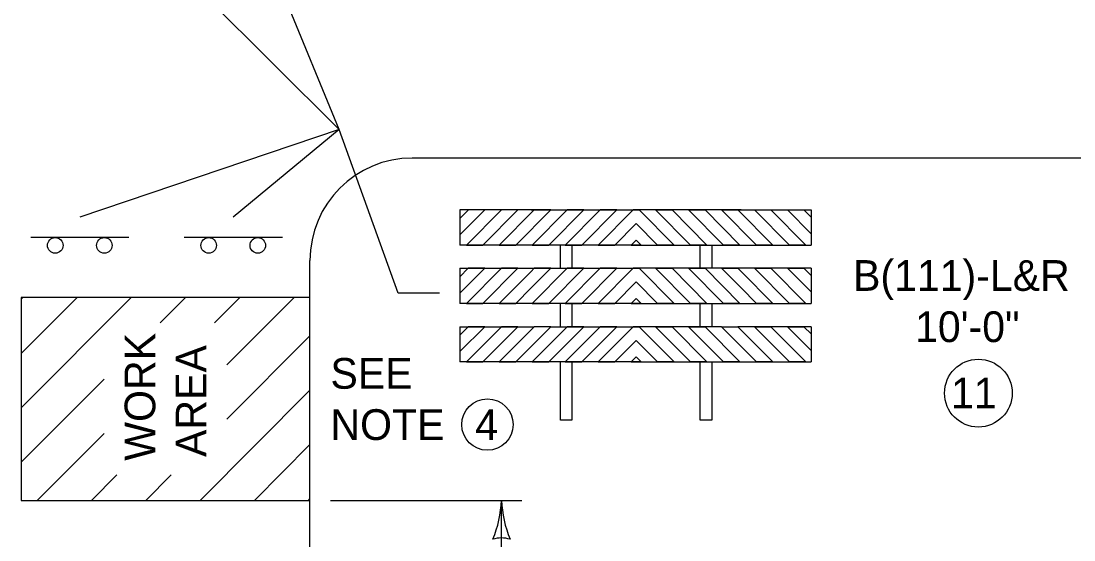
# Model space of a CAD drawing. Extents: x 49991.4 to 50021, y 49987.6 to 50011.4.
# Drawn here: x 50001.903 to 50003.961, y 49992.395 to 49993.408 of the extents above; entities that cross this region are included whole.
import ezdxf

# ---------------------------------------------------------------- set-up
doc = ezdxf.new("R2010")
doc.units = 0
for name, color, linetype in [('Level 1', 7, 'Continuous'), ('Level 2', 7, 'Continuous'), ('Level 3', 7, 'Continuous')]:
    doc.layers.add(name, color=color, linetype=linetype)

# ---------------------------------------------------------------- blocks, each defined once
blk = doc.blocks.new('ARR')
at = {"layer": 'Level 3'}
for centre, radius, start, end in [((1.53, 37.02), 37.05, 247.456, 267.6395), ((-21.37, 0), 9.13, 342.1388, 17.8612), ((1.92, -38.79), 38.83, 92.8273, 112.0772)]:
    blk.add_arc(centre, radius, start, end, dxfattribs=at)

msp = doc.modelspace()

# ---------------------------------------------------------------- linework, layer by layer
at = {"layer": 'Level 1'}
for p, q in [((50004.4673, 49993.1404), (50002.6673, 49993.1404)), ((50002.8854, 49993.039), (50002.7604, 49993.039)), ((50002.7604, 49992.9902), (50002.8092, 49993.039)), ((50002.7604, 49993.0224), (50002.777, 49993.039)), ((50002.7604, 49993.039), (50002.7604, 49992.9706)), ((50002.773, 49992.9706), (50002.8414, 49993.039)), ((50002.8052, 49992.9706), (50002.8736, 49993.039)), ((50002.8374, 49992.9706), (50002.9058, 49993.039)), ((50002.9058, 49993.039), (50002.8659, 49993.039)), ((50002.8696, 49992.9706), (50002.938, 49993.039)), ((50002.8997, 49993.039), (50003.1049, 49993.039)), ((50002.9019, 49992.9706), (50002.9703, 49993.039)), ((50002.9703, 49993.039), (50002.9019, 49992.9706)), ((50002.9342, 49992.9706), (50003.0026, 49993.039)), ((50002.9342, 49992.9706), (50003.0026, 49993.039)), ((50002.9664, 49992.9706), (50003.0348, 49993.039)), ((50003.0348, 49993.039), (50002.9664, 49992.9706)), ((50002.9986, 49992.9706), (50003.067, 49993.039)), ((50002.9986, 49992.9706), (50003.067, 49993.039)), ((50003.0309, 49992.9706), (50003.0993, 49993.039)), ((50003.0993, 49993.039), (50003.0309, 49992.9706)), ((50003.1049, 49993.039), (50003.0993, 49993.039)), ((50003.3101, 49993.039), (50003.1049, 49993.039)), ((50003.1049, 49993.039), (50003.1105, 49993.039)), ((50003.1105, 49993.039), (50003.1789, 49992.9706)), ((50003.1789, 49992.9706), (50003.1105, 49993.039)), ((50003.2111, 49992.9706), (50003.1427, 49993.039)), ((50003.2111, 49992.9706), (50003.1427, 49993.039)), ((50003.2434, 49992.9706), (50003.175, 49993.039)), ((50003.175, 49993.039), (50003.2434, 49992.9706)), ((50003.2756, 49992.9706), (50003.2072, 49993.039)), ((50003.2756, 49992.9706), (50003.2072, 49993.039)), ((50003.3079, 49992.9706), (50003.2395, 49993.039)), ((50003.2395, 49993.039), (50003.3079, 49992.9706)), ((50003.3401, 49992.9706), (50003.2717, 49993.039)), ((50003.3723, 49992.9706), (50003.3039, 49993.039)), ((50003.3039, 49993.039), (50003.3438, 49993.039)), ((50003.3243, 49993.039), (50003.4469, 49993.039)), ((50003.4045, 49992.9706), (50003.3361, 49993.039)), ((50003.4367, 49992.9706), (50003.3683, 49993.039)), ((50003.4469, 49992.9927), (50003.4005, 49993.039)), ((50003.4469, 49993.0249), (50003.4327, 49993.039)), ((50003.4469, 49993.039), (50003.4469, 49992.9706)), ((50003.0631, 49992.9706), (50003.1049, 49993.0124)), ((50003.0631, 49992.9706), (50003.1049, 49993.0124)), ((50003.1467, 49992.9706), (50003.1049, 49993.0124)), ((50003.1467, 49992.9706), (50003.1049, 49993.0124)), ((50002.0173, 49992.985), (50001.9213, 49992.985)), ((50002.1133, 49992.985), (50002.0173, 49992.985)), ((50002.3173, 49992.985), (50002.2213, 49992.985)), ((50002.4133, 49992.985), (50002.3173, 49992.985)), ((50003.1049, 49992.9706), (50002.8997, 49992.9706)), ((50002.9567, 49992.9251), (50002.9567, 49992.9706)), ((50003.0954, 49992.9706), (50003.1049, 49992.9801)), ((50003.1049, 49992.9801), (50003.0954, 49992.9706)), ((50003.0954, 49992.9706), (50003.1049, 49992.9706)), ((50003.1144, 49992.9706), (50003.1049, 49992.9801)), ((50003.1049, 49992.9801), (50003.1144, 49992.9706)), ((50003.1049, 49992.9706), (50003.3101, 49992.9706)), ((50003.1144, 49992.9706), (50003.1049, 49992.9706)), ((50003.2303, 49992.9251), (50003.2303, 49992.9706)), ((50002.4673, 49988.1586), (50002.4673, 49992.9404)), ((50002.7604, 49992.9086), (50002.7768, 49992.9251)), ((50002.7604, 49992.8764), (50002.8091, 49992.9251)), ((50002.7604, 49992.9251), (50002.8997, 49992.9251)), ((50002.7604, 49992.9251), (50002.7604, 49992.8567)), ((50002.773, 49992.8567), (50002.8414, 49992.9251)), ((50002.8052, 49992.8567), (50002.8736, 49992.9251)), ((50002.8997, 49992.8867), (50002.938, 49992.9251)), ((50002.8997, 49992.9251), (50003.1049, 49992.9251)), ((50002.9019, 49992.8567), (50002.9703, 49992.9251)), ((50002.9703, 49992.9251), (50002.9019, 49992.8567)), ((50002.9342, 49992.8567), (50003.0026, 49992.9251)), ((50002.9342, 49992.8567), (50003.0026, 49992.9251)), ((50002.9664, 49992.8567), (50003.0348, 49992.9251)), ((50003.0348, 49992.9251), (50002.9664, 49992.8567)), ((50002.9986, 49992.8567), (50003.067, 49992.9251)), ((50002.9986, 49992.8567), (50003.067, 49992.9251)), ((50003.0309, 49992.8567), (50003.0993, 49992.9251)), ((50003.0993, 49992.9251), (50003.0309, 49992.8567)), ((50003.1049, 49992.9251), (50003.0993, 49992.9251)), ((50003.3101, 49992.9251), (50003.1049, 49992.9251)), ((50003.1049, 49992.9251), (50003.1105, 49992.9251)), ((50003.1789, 49992.8567), (50003.1105, 49992.9251)), ((50003.1105, 49992.9251), (50003.1789, 49992.8567)), ((50003.2111, 49992.8567), (50003.1427, 49992.9251)), ((50003.2111, 49992.8567), (50003.1427, 49992.9251)), ((50003.2434, 49992.8567), (50003.175, 49992.9251)), ((50003.175, 49992.9251), (50003.2434, 49992.8567)), ((50003.2756, 49992.8567), (50003.2072, 49992.9251)), ((50003.2756, 49992.8567), (50003.2072, 49992.9251)), ((50003.3079, 49992.8567), (50003.2395, 49992.9251)), ((50003.2395, 49992.9251), (50003.3079, 49992.8567)), ((50003.3101, 49992.8867), (50003.2717, 49992.9251)), ((50003.4469, 49992.9251), (50003.3101, 49992.9251)), ((50003.4046, 49992.8567), (50003.3362, 49992.9251)), ((50003.4368, 49992.8567), (50003.3684, 49992.9251)), ((50003.4469, 49992.8789), (50003.4007, 49992.9251)), ((50003.4469, 49992.9111), (50003.4329, 49992.9251)), ((50003.4469, 49992.9251), (50003.4469, 49992.8567)), ((50002.8374, 49992.8567), (50002.8997, 49992.9189)), ((50003.3723, 49992.8567), (50003.3101, 49992.9189)), ((50002.8696, 49992.8567), (50002.8997, 49992.8867)), ((50003.0631, 49992.8567), (50003.1049, 49992.8984)), ((50003.0631, 49992.8567), (50003.1049, 49992.8984)), ((50003.1467, 49992.8567), (50003.1049, 49992.8984)), ((50003.1467, 49992.8567), (50003.1049, 49992.8984)), ((50003.3401, 49992.8567), (50003.3101, 49992.8867)), ((50002.4673, 49992.868), (50001.9025, 49992.868)), ((50001.9025, 49992.868), (50001.9025, 49992.4721)), ((50001.9025, 49992.8646), (50001.9059, 49992.868)), ((50001.9025, 49992.7585), (50002.012, 49992.868)), ((50001.9025, 49992.6524), (50002.118, 49992.868)), ((50002.1746, 49992.8185), (50002.2241, 49992.868)), ((50002.2807, 49992.8185), (50002.3302, 49992.868)), ((50002.3049, 49992.7366), (50002.4362, 49992.868)), ((50003.0954, 49992.8567), (50003.1049, 49992.8662)), ((50003.1049, 49992.8662), (50003.0954, 49992.8567)), ((50003.1144, 49992.8567), (50003.1049, 49992.8662)), ((50003.1049, 49992.8662), (50003.1144, 49992.8567)), ((50003.1049, 49992.8567), (50002.7604, 49992.8567)), ((50003.0954, 49992.8567), (50003.1049, 49992.8567)), ((50003.1049, 49992.8567), (50003.4469, 49992.8567)), ((50003.1144, 49992.8567), (50003.1049, 49992.8567)), ((50002.7604, 49992.7947), (50002.7768, 49992.8111)), ((50002.7604, 49992.7624), (50002.8091, 49992.8111)), ((50002.7604, 49992.7624), (50002.8091, 49992.8111)), ((50002.7768, 49992.8111), (50002.7604, 49992.7947)), ((50002.7604, 49992.8111), (50002.7604, 49992.7427)), ((50002.773, 49992.7427), (50002.8414, 49992.8111)), ((50002.8414, 49992.8111), (50002.773, 49992.7427)), ((50002.8052, 49992.7427), (50002.8736, 49992.8111)), ((50002.8052, 49992.7427), (50002.8736, 49992.8111)), ((50002.8374, 49992.7427), (50002.9058, 49992.8111)), ((50002.9058, 49992.8111), (50002.8374, 49992.7427)), ((50002.8696, 49992.7427), (50002.938, 49992.8111)), ((50002.8696, 49992.7427), (50002.938, 49992.8111)), ((50002.9019, 49992.7427), (50002.9703, 49992.8111)), ((50002.9703, 49992.8111), (50002.9019, 49992.7427)), ((50002.9342, 49992.7427), (50003.0026, 49992.8111)), ((50002.9342, 49992.7427), (50003.0026, 49992.8111)), ((50002.938, 49992.8111), (50003.1049, 49992.8111)), ((50002.9664, 49992.7427), (50003.0348, 49992.8111)), ((50003.0348, 49992.8111), (50002.9664, 49992.7427)), ((50002.9986, 49992.7427), (50003.067, 49992.8111)), ((50002.9986, 49992.7427), (50003.067, 49992.8111)), ((50003.0309, 49992.7427), (50003.0993, 49992.8111)), ((50003.0993, 49992.8111), (50003.0309, 49992.7427)), ((50003.1049, 49992.8111), (50003.0993, 49992.8111)), ((50003.2717, 49992.8111), (50003.1049, 49992.8111)), ((50003.1049, 49992.8111), (50003.1105, 49992.8111)), ((50003.1789, 49992.7427), (50003.1105, 49992.8111)), ((50003.1105, 49992.8111), (50003.1789, 49992.7427)), ((50003.2111, 49992.7427), (50003.1427, 49992.8111)), ((50003.2111, 49992.7427), (50003.1427, 49992.8111)), ((50003.2434, 49992.7427), (50003.175, 49992.8111)), ((50003.175, 49992.8111), (50003.2434, 49992.7427)), ((50003.2756, 49992.7427), (50003.2072, 49992.8111)), ((50003.2756, 49992.7427), (50003.2072, 49992.8111)), ((50003.3079, 49992.7427), (50003.2395, 49992.8111)), ((50003.2395, 49992.8111), (50003.3079, 49992.7427)), ((50003.3401, 49992.7427), (50003.2717, 49992.8111)), ((50003.3401, 49992.7427), (50003.2717, 49992.8111)), ((50003.3723, 49992.7427), (50003.3039, 49992.8111)), ((50003.3039, 49992.8111), (50003.3723, 49992.7427)), ((50003.4046, 49992.7427), (50003.3362, 49992.8111)), ((50003.4046, 49992.7427), (50003.3362, 49992.8111)), ((50003.4368, 49992.7427), (50003.3684, 49992.8111)), ((50003.3684, 49992.8111), (50003.4368, 49992.7427)), ((50003.4469, 49992.7649), (50003.4007, 49992.8111)), ((50003.4469, 49992.7649), (50003.4007, 49992.8111)), ((50003.4469, 49992.7972), (50003.4329, 49992.8111)), ((50003.4329, 49992.8111), (50003.4469, 49992.7972)), ((50003.4469, 49992.8111), (50003.4469, 49992.7427)), ((50002.3049, 49992.6306), (50002.4673, 49992.793)), ((50003.0631, 49992.7427), (50003.1049, 49992.7845)), ((50003.0631, 49992.7427), (50003.1049, 49992.7845)), ((50003.1467, 49992.7427), (50003.1049, 49992.7845)), ((50003.1467, 49992.7427), (50003.1049, 49992.7845)), ((50003.1049, 49992.7427), (50002.7604, 49992.7427)), ((50003.0954, 49992.7427), (50003.1049, 49992.7523)), ((50003.1049, 49992.7523), (50003.0954, 49992.7427)), ((50003.0954, 49992.7427), (50003.1049, 49992.7427)), ((50003.1144, 49992.7427), (50003.1049, 49992.7523)), ((50003.1049, 49992.7523), (50003.1144, 49992.7427)), ((50003.1049, 49992.7427), (50003.4469, 49992.7427)), ((50003.1144, 49992.7427), (50003.1049, 49992.7427)), ((50001.9025, 49992.5464), (50002.0649, 49992.7088)), ((50002.2525, 49992.4721), (50002.4673, 49992.6869)), ((50001.9343, 49992.4721), (50002.0649, 49992.6027)), ((50002.3586, 49992.4721), (50002.4673, 49992.5809)), ((50002.0404, 49992.4721), (50002.0899, 49992.5216)), ((50002.1464, 49992.4721), (50002.1959, 49992.5216)), ((50001.9025, 49992.4721), (50002.4673, 49992.4721)), ((50002.4646, 49992.4721), (50002.4673, 49992.4748))]:
    msp.add_line(p, q, dxfattribs=at)
for points in [[(50002.7604, 49992.9902), (50002.8092, 49993.039)], [(50002.8092, 49993.039), (50002.777, 49993.039), (50002.7604, 49993.0224)], [(50002.8736, 49993.039), (50002.8659, 49993.039), (50002.8414, 49993.039), (50002.773, 49992.9706), (50002.8052, 49992.9706), (50002.8736, 49993.039)], [(50002.8374, 49992.9706), (50002.8696, 49992.9706), (50002.938, 49993.039), (50002.9058, 49993.039), (50002.8374, 49992.9706)], [(50003.0026, 49993.039), (50002.9703, 49993.039)], [(50003.1467, 49992.9706), (50003.1789, 49992.9706), (50003.1105, 49993.039), (50003.1049, 49993.039), (50003.0993, 49993.039), (50003.0309, 49992.9706), (50003.0631, 49992.9706), (50003.1049, 49993.0124), (50003.1467, 49992.9706)], [(50003.067, 49993.039), (50003.0348, 49993.039)], [(50003.1427, 49993.039), (50003.175, 49993.039)], [(50003.2072, 49993.039), (50003.2395, 49993.039)], [(50003.3723, 49992.9706), (50003.3401, 49992.9706), (50003.2717, 49993.039), (50003.3039, 49993.039), (50003.3723, 49992.9706)], [(50003.3361, 49993.039), (50003.3438, 49993.039), (50003.3683, 49993.039), (50003.4367, 49992.9706), (50003.4045, 49992.9706), (50003.3361, 49993.039)], [(50003.4469, 49992.9927), (50003.4005, 49993.039)], [(50003.4005, 49993.039), (50003.4327, 49993.039), (50003.4469, 49993.0249)], [(50002.7604, 49993.0224), (50002.7604, 49992.9902)], [(50003.4469, 49993.0249), (50003.4469, 49992.9927)], [(50002.8997, 49992.9706), (50002.7604, 49992.9706)], [(50002.9019, 49992.9706), (50002.9342, 49992.9706)], [(50002.9664, 49992.9706), (50002.9986, 49992.9706)], [(50002.9795, 49992.9706), (50002.9795, 49992.9251)], [(50003.0309, 49992.9706), (50003.0631, 49992.9706)], [(50003.0954, 49992.9706), (50003.1049, 49992.9706), (50003.1144, 49992.9706), (50003.1049, 49992.9801), (50003.0954, 49992.9706)], [(50003.1789, 49992.9706), (50003.1467, 49992.9706)], [(50003.2434, 49992.9706), (50003.2111, 49992.9706)], [(50003.2531, 49992.9706), (50003.2531, 49992.9251)], [(50003.3079, 49992.9706), (50003.2756, 49992.9706)], [(50003.3101, 49992.9706), (50003.4469, 49992.9706)], [(50002.7604, 49992.8764), (50002.8091, 49992.9251)], [(50002.8091, 49992.9251), (50002.7768, 49992.9251), (50002.7604, 49992.9086)], [(50002.8736, 49992.9251), (50002.8414, 49992.9251), (50002.773, 49992.8567), (50002.8052, 49992.8567), (50002.8736, 49992.9251)], [(50002.8374, 49992.8567), (50002.8696, 49992.8567), (50002.8997, 49992.8867), (50002.938, 49992.9251), (50002.9111, 49992.9251), (50002.9058, 49992.9251), (50002.8997, 49992.9189), (50002.8374, 49992.8567)], [(50003.0026, 49992.9251), (50002.9703, 49992.9251)], [(50003.1467, 49992.8567), (50003.1789, 49992.8567), (50003.1105, 49992.9251), (50003.1049, 49992.9251), (50003.0993, 49992.9251), (50003.0309, 49992.8567), (50003.0631, 49992.8567), (50003.1049, 49992.8984), (50003.1467, 49992.8567)], [(50003.067, 49992.9251), (50003.0348, 49992.9251)], [(50003.1427, 49992.9251), (50003.175, 49992.9251)], [(50003.2072, 49992.9251), (50003.2395, 49992.9251)], [(50003.3723, 49992.8567), (50003.3401, 49992.8567), (50003.3101, 49992.8867), (50003.2717, 49992.9251), (50003.2987, 49992.9251), (50003.3039, 49992.9251), (50003.3101, 49992.9189), (50003.3723, 49992.8567)], [(50003.3362, 49992.9251), (50003.3684, 49992.9251), (50003.4368, 49992.8567), (50003.4046, 49992.8567), (50003.3362, 49992.9251)], [(50003.4469, 49992.8789), (50003.4007, 49992.9251)], [(50003.4007, 49992.9251), (50003.4329, 49992.9251), (50003.4469, 49992.9111)], [(50002.7604, 49992.9086), (50002.7604, 49992.8764)], [(50003.4469, 49992.9111), (50003.4469, 49992.8789)], [(50003.0954, 49992.8567), (50003.1049, 49992.8567), (50003.1144, 49992.8567), (50003.1049, 49992.8662), (50003.0954, 49992.8567)], [(50002.9019, 49992.8567), (50002.9342, 49992.8567)], [(50002.9567, 49992.8111), (50002.9567, 49992.8567)], [(50002.9664, 49992.8567), (50002.9986, 49992.8567)], [(50002.9795, 49992.8567), (50002.9795, 49992.8111)], [(50003.0309, 49992.8567), (50003.0631, 49992.8567)], [(50003.1789, 49992.8567), (50003.1467, 49992.8567)], [(50003.2434, 49992.8567), (50003.2111, 49992.8567)], [(50003.2303, 49992.8111), (50003.2303, 49992.8567)], [(50003.2531, 49992.8567), (50003.2531, 49992.8111)], [(50003.3079, 49992.8567), (50003.2756, 49992.8567)], [(50002.7604, 49992.8111), (50002.9058, 49992.8111)], [(50002.8091, 49992.8111), (50002.7768, 49992.8111)], [(50002.8736, 49992.8111), (50002.8414, 49992.8111)], [(50002.938, 49992.8111), (50002.9058, 49992.8111)], [(50003.0026, 49992.8111), (50002.9703, 49992.8111)], [(50003.1467, 49992.7427), (50003.1789, 49992.7427), (50003.1105, 49992.8111), (50003.1049, 49992.8111), (50003.0993, 49992.8111), (50003.0309, 49992.7427), (50003.0631, 49992.7427), (50003.1049, 49992.7845), (50003.1467, 49992.7427)], [(50003.067, 49992.8111), (50003.0348, 49992.8111)], [(50003.1427, 49992.8111), (50003.175, 49992.8111)], [(50003.2072, 49992.8111), (50003.2395, 49992.8111)], [(50003.2717, 49992.8111), (50003.3039, 49992.8111)], [(50003.4469, 49992.8111), (50003.3039, 49992.8111)], [(50003.3362, 49992.8111), (50003.3684, 49992.8111)], [(50003.4007, 49992.8111), (50003.4329, 49992.8111)], [(50002.7604, 49992.7947), (50002.7604, 49992.7624)], [(50003.4469, 49992.7972), (50003.4469, 49992.7649)], [(50002.773, 49992.7427), (50002.8052, 49992.7427)], [(50002.8374, 49992.7427), (50002.8696, 49992.7427)], [(50002.9019, 49992.7427), (50002.9342, 49992.7427)], [(50002.9795, 49992.7426), (50002.9795, 49992.6286), (50002.9567, 49992.6286), (50002.9567, 49992.7426)], [(50002.9664, 49992.7427), (50002.9986, 49992.7427)], [(50003.0309, 49992.7427), (50003.0631, 49992.7427)], [(50003.0954, 49992.7427), (50003.1049, 49992.7427), (50003.1144, 49992.7427), (50003.1049, 49992.7523), (50003.0954, 49992.7427)], [(50003.1789, 49992.7427), (50003.1467, 49992.7427)], [(50003.2434, 49992.7427), (50003.2111, 49992.7427)], [(50003.2531, 49992.7426), (50003.2531, 49992.6286), (50003.2303, 49992.6286), (50003.2303, 49992.7426)], [(50003.3079, 49992.7427), (50003.2756, 49992.7427)], [(50003.3723, 49992.7427), (50003.3401, 49992.7427)], [(50003.4368, 49992.7427), (50003.4046, 49992.7427)]]:
    msp.add_lwpolyline(points, dxfattribs=at)
for centre in [(50001.9693, 49992.9698), (50002.0653, 49992.9698), (50002.2693, 49992.9698), (50002.3653, 49992.9698)]:
    msp.add_circle(centre, 0.0152, dxfattribs=at)
msp.add_arc((50002.6673, 49992.9404), 0.2, 90, 180, dxfattribs=at)
at = {"layer": 'Level 2'}
for centre, radius in [((50003.7739, 49992.6814), 0.0662), ((50002.8142, 49992.62), 0.0501)]:
    msp.add_circle(centre, radius, dxfattribs=at)
at = {"layer": 'Level 3'}
for p, q in [((50002.5242, 49993.1959), (50002.0173, 49993.7005)), ((50002.5242, 49993.1959), (50002.3173, 49993.7005)), ((50002.5242, 49993.1959), (50002.0173, 49993.025)), ((50002.5242, 49993.1959), (50002.3173, 49993.025)), ((50002.6394, 49992.8764), (50002.5242, 49993.1959)), ((50002.7204, 49992.8764), (50002.6394, 49992.8764)), ((50002.5073, 49992.4721), (50002.8816, 49992.4721)), ((50002.8416, 49992.0977), (50002.8416, 49992.4721))]:
    msp.add_line(p, q, dxfattribs=at)

# ---------------------------------------------------------------- block references
at = {"layer": 'Level 3', "xscale": 0.006, "yscale": 0.006, "rotation": 90}
msp.add_blockref('ARR', (50002.8416, 49992.4721), dxfattribs=at)

# ---------------------------------------------------------------- texts
at = {"layer": 'Level 2'}
for s, height, p in [('B(111)-L&R', 0.06, (50003.5289, 49992.8811)), ('10\'-0"', 0.06, (50003.6501, 49992.7811)), ('SEE', 0.06, (50002.5073, 49992.69)), ('11', 0.06006, (50003.7204, 49992.6515)), ('NOTE', 0.06, (50002.5073, 49992.59)), ('4', 0.06, (50002.7903, 49992.59))]:
    msp.add_text(s, height=height, dxfattribs=at).set_placement(p)
for s, p in [('WORK', (50002.1649, 49992.5494)), ('AREA', (50002.2649, 49992.5567))]:
    msp.add_text(s, height=0.06, rotation=90, dxfattribs=at).set_placement(p)

doc.saveas('drawing.dxf')
